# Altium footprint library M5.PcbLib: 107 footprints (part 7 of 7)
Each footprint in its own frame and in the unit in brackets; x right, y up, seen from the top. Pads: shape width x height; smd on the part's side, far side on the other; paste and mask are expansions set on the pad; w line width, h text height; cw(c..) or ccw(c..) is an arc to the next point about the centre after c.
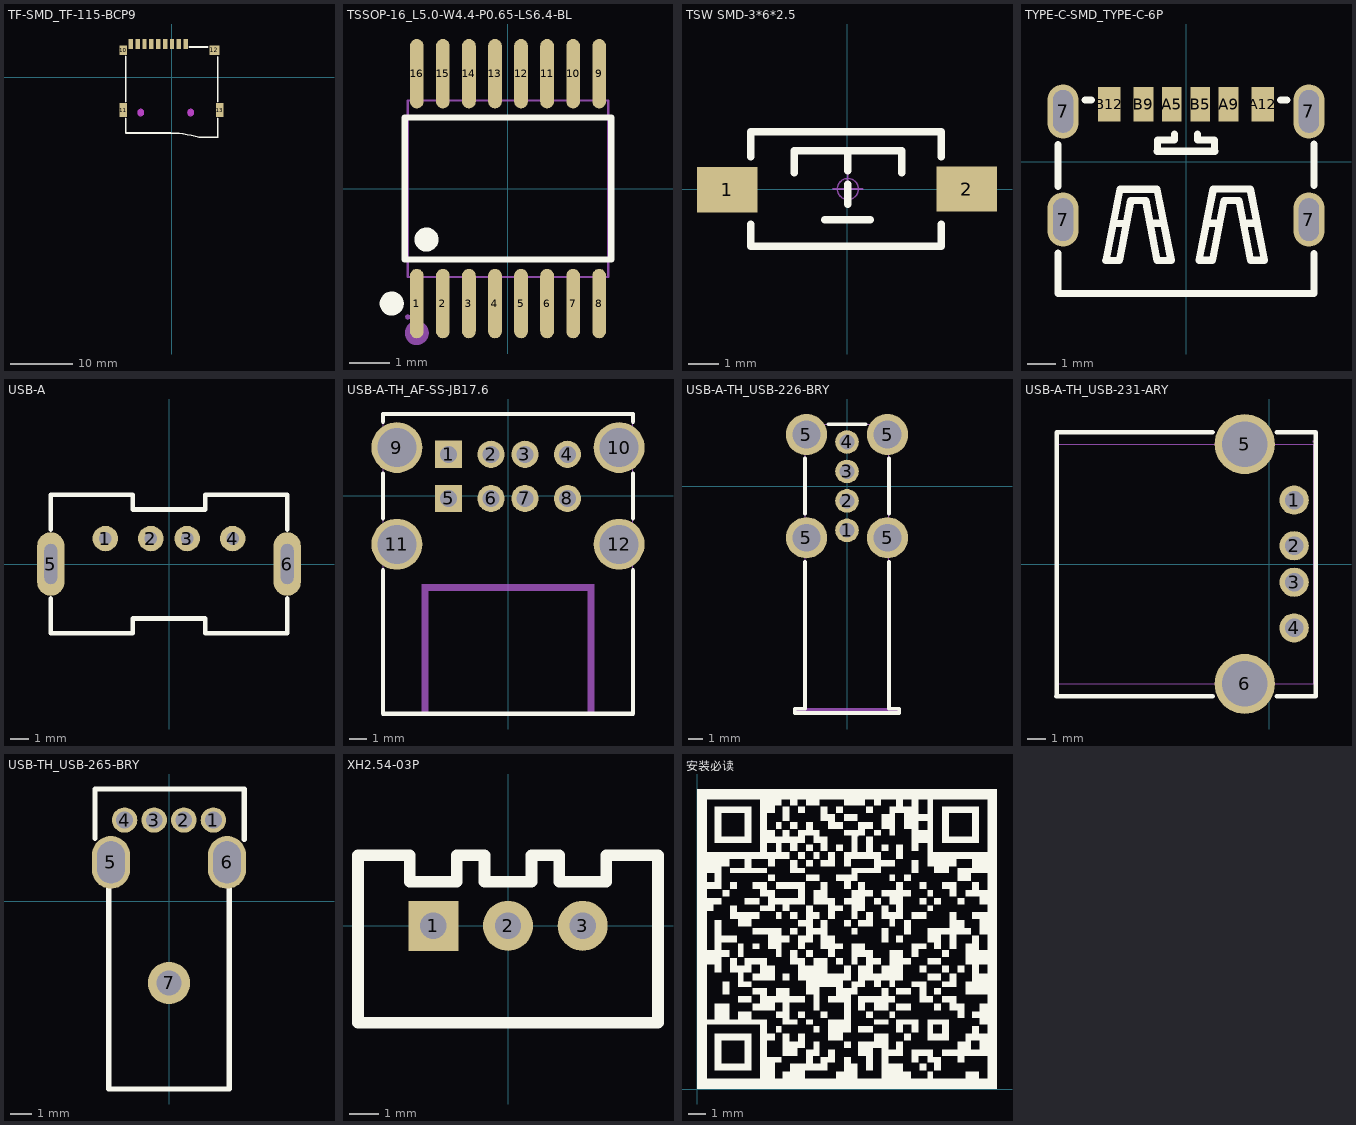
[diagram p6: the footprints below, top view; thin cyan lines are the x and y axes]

## TF-SMD_TF-115-BCP9 [mm]
pads (13):
  rect 0.7x1.6 smd: 1(2.25,5.3) 2(1.15,5.3) 3(0.05,5.3) 4(-1.05,5.3) 5(-2.15,5.3) 6(-3.25,5.3) 7(-4.35,5.3) 8(-5.45,5.3) 9(-6.55,5.3)
  rect 1.2x1.5 smd: 10(-7.75,4.3)
  rect 1.2x2.2 smd: 11(-7.75,-5.3) 13(7.75,-5.3)
  rect 1.6x1.5 smd: 12(6.85,4.3)
Top Overlay:
  lines w0.254: -7.38,-6.631 -7.38,-8.98 -2.22,-8.98 -0.14,-8.98 cw(c-0.424,-25.511) 4.41,-9.7 7.42,-9.69 ; -7.38,-3.969 -7.38,3.319 ; 2.831,4.81 5.819,4.81 ; 7.41,-9.7 7.42,-9.69 ; 7.42,-6.631 7.42,-9.69 ; 7.42,-3.969 7.42,3.28
Keep-Out Layer:
  circle w0.025: c3.05,-5.7 r0.5
  circle w0.025: c-4.95,-5.7 r0.5
  board cut-out: 3.56,-5.7 3.521,-5.895 3.411,-6.06 3.245,-6.171 3.05,-6.21 2.855,-6.171 2.69,-6.06 2.579,-5.895 2.54,-5.7 2.579,-5.505 2.69,-5.34 2.855,-5.229 3.05,-5.19 3.245,-5.229 3.411,-5.34 3.521,-5.505
  board cut-out: -4.44,-5.7 -4.479,-5.895 -4.589,-6.06 -4.755,-6.171 -4.95,-6.21 -5.145,-6.171 -5.31,-6.06 -5.421,-5.895 -5.46,-5.7 -5.421,-5.505 -5.31,-5.34 -5.145,-5.229 -4.95,-5.19 -4.755,-5.229 -4.589,-5.34 -4.479,-5.505
Keep-Out Layer:
  region: 3.56,-5.7 3.521,-5.895 3.411,-6.06 3.245,-6.171 3.05,-6.21 2.855,-6.171 2.69,-6.06 2.579,-5.895 2.54,-5.7 2.579,-5.505 2.69,-5.34 2.855,-5.229 3.05,-5.19 3.245,-5.229 3.411,-5.34 3.521,-5.505
  region: -4.44,-5.7 -4.479,-5.895 -4.589,-6.06 -4.755,-6.171 -4.95,-6.21 -5.145,-6.171 -5.31,-6.06 -5.421,-5.895 -5.46,-5.7 -5.421,-5.505 -5.31,-5.34 -5.145,-5.229 -4.95,-5.19 -4.755,-5.229 -4.589,-5.34 -4.479,-5.505
Mechanical 1:
  circle w0.025: c3.05,-5.7 r0.5
  circle w0.025: c-4.95,-5.7 r0.5
Mechanical 6:
  circle w0.4: c-4.95,-5.7 r0.2
  circle w0.4: c3.05,-5.7 r0.2
3D body: height 1.8, standoff -0.6, extent -8.025,-9.8 8.125,5.3

## TSSOP-16_L5.0-W4.4-P0.65-LS6.4-BL [mm]
pads (16):
  oval 0.343x1.731 smd: 1(-2.275,-2.866) 2(-1.625,-2.866) 3(-0.975,-2.866) 4(-0.325,-2.866) 5(0.325,-2.866) 6(0.975,-2.866) 7(1.625,-2.866) 8(2.275,-2.866) 9(2.275,2.866) 10(1.625,2.866) 11(0.975,2.866) 12(0.325,2.866) 13(-0.325,2.866) 14(-0.975,2.866) 15(-1.625,2.866) 16(-2.275,2.866)
Top Overlay:
  circle w0.3: c-2.032,-1.27 r0.15
  circle w0.3: c-2.899,-2.866 r0.15
  lines w0.152: -2.576,-1.771 -2.576,1.772 2.576,1.772 2.576,-1.771 -2.576,-1.771
Mechanical 6:
  circle w0.3: c-2.275,-3.6 r0.15
Mechanical 15:
  drawing of 37 lines, arcs and shapes, not listed

## TSW SMD-3*6*2.5 [mm]
pads (2):
  rect 2x1.5 smd: 1(-3.966,-0.01) 2(3.966,0.01)
Top Overlay:
  lines w0.254: -3.182,-1.158 -3.182,-1.89 3.118,-1.89 3.118,-1.158 ; -3.182,1.077 -3.182,1.91 3.118,1.91 3.118,1.077 ; -1.749,0.543 -1.749,1.28 1.807,1.28 1.807,0.543 ; -0.733,-1.006 0.766,-1.006 ; 0.029,-0.498 0.029,0.162 ; 0.029,0.62 0.029,1.28
Mechanical 15:
  circle w0.05: c0.029,0.01 r0.35
  lines w0.05: -0.471,0.01 0.529,0.01 ; 0.029,-0.49 0.029,0.51
3D body: height 2.59, standoff -0.03, extent -3.971,-1.867 4.029,1.633

## TYPE-C-SMD_TYPE-C-6P [mm]
pads (10):
  oval 1.1x1.9 hole 0.7 slot 1.5 at 90 deg: 7(-4.32,-2.025) 7(-4.32,1.775) 7(4.32,-2.025) 7(4.32,1.775)
  rect 0.7x1.2 smd paste-100 mask+0.051: A5(-0.5,2.025) A9(1.5,2.025) B5(0.5,2.025) B9(-1.5,2.025)
  rect 0.8x1.2 smd paste-100 mask+0.051: A12(2.7,2.025) B12(-2.7,2.025)
Top Overlay:
  lines w0.25: -4.501,-3.226 -4.501,-3.203 -4.501,-4.626 4.501,-4.626 4.501,-3.226 ; -4.5,-0.867 -4.5,0.575 -4.5,0.617 ; -3.541,2.175 -3.329,2.175 ; -1.01,0.375 1.01,0.375 ; -1,0.375 -1,0.775 -0.4,0.775 -0.4,0.975 ; 0.4,0.975 0.4,0.775 1,0.775 1,0.375 ; 3.329,2.175 3.541,2.175 ; 4.5,-0.825 4.5,0.625
  lines w0.254: -2.518,-2.158 -2.119,-2.158 ; -1.219,-2.157 -0.819,-2.157 ; 0.759,-2.153 1.158,-2.153 ; 2.058,-2.152 2.458,-2.152 ; -2.818,-3.458 -2.32,-0.956 -1.019,-0.956 -0.519,-3.458 -1.014,-3.458 -1.413,-1.358 -1.941,-1.358 -2.343,-3.458 -2.818,-3.458 ; 0.459,-3.453 0.957,-0.951 2.257,-0.951 2.758,-3.453 2.263,-3.453 1.864,-1.353 1.335,-1.353 0.934,-3.453 0.459,-3.453
Top Paste:
  drawing of 10 lines, arcs and shapes, not listed

## USB-A [mm]
pads (6):
  round 1.4 hole 0.7: 1(-3.5,1.4) 2(-1,1.4) 3(1,1.4) 4(3.5,1.4)
  oval 1.5x3.5 hole 0.7 slot 2.2 at 90 deg: 5(-6.5,0) 6(6.5,0)
Top Overlay:
  lines w0.254: -6.5,-1.9 -6.5,-3.8 -2,-3.8 -2,-3 2,-3 2,-3.8 6.5,-3.8 6.5,-1.9 ; -6.5,1.9 -6.5,3.8 -2,3.8 -2,3 2,3 2,3.8 6.5,3.8 6.5,1.9

## USB-A-TH_AF-SS-JB17.6 [mm]
pads (12):
  rect 1.6x1.6 hole 1 paste+0 mask+0.05: 1(-3.5,2.45) 5(-3.5,-0.15)
  round 1.6 hole 1 paste+0 mask+0.05: 2(-1,2.45) 3(1,2.45) 4(3.5,2.45) 6(-1,-0.15) 7(1,-0.15) 8(3.5,-0.15)
  round 3 hole 2.3 paste+0 mask+0.05: 9(-6.55,2.85) 10(6.55,2.85) 11(-6.55,-2.85) 12(6.55,-2.85)
Top Overlay:
  lines w0.254: -7.366,-4.376 -7.366,-12.827 7.366,-12.827 7.366,-4.376 ; -7.366,-1.324 -7.366,1.324 ; -7.366,4.376 -7.366,4.826 7.366,4.826 7.366,4.376 ; 7.366,-1.324 7.366,1.324
Mechanical 6:
  region: -5.08,-12.827 -5.08,-5.207 5.08,-5.207 5.08,-12.827 4.699,-12.827 4.699,-5.588 -4.699,-5.588 -4.699,-12.827
Mechanical 15:
  region: -7.285,4.75 -7.304,4.704 -7.35,4.685 -7.396,4.704 -7.415,4.75 -7.396,4.796 -7.35,4.815 -7.304,4.796
  region: 3.2,0 3.8,0 3.8,-0.3 3.2,-0.3
  region: 0.7,0 1.3,0 1.3,-0.3 0.7,-0.3
  region: -1.3,0 -0.7,0 -0.7,-0.3 -1.3,-0.3
  region: -3.8,0 -3.2,0 -3.2,-0.3 -3.8,-0.3
  region: 3.2,2.6 3.8,2.6 3.8,2.3 3.2,2.3
  region: 0.7,2.6 1.3,2.6 1.3,2.3 0.7,2.3
  region: -1.3,2.6 -0.7,2.6 -0.7,2.3 -1.3,2.3
  region: -3.8,2.6 -3.2,2.6 -3.2,2.3 -3.8,2.3
  region: -6.7,-1.85 -6.4,-1.85 -6.4,-3.85 -6.7,-3.85
  region: -6.7,3.85 -6.4,3.85 -6.4,1.85 -6.7,1.85
  region: 6.4,-1.85 6.7,-1.85 6.7,-3.85 6.4,-3.85
  region: 6.4,3.85 6.7,3.85 6.7,1.85 6.4,1.85
  lines w0.051: -7.35,-12.85 7.35,-12.85 7.35,4.75 -7.35,4.75 -7.35,-12.85

## USB-A-TH_USB-226-BRY [mm]
pads (8):
  round 1.6 hole 1: 1(0,-3) 2(0,-1) 3(0,1) 4(0,3)
  round 2.8 hole 1.9: 5(-2.75,-3.5) 5(-2.75,3.5) 5(2.75,-3.5) 5(2.75,3.5)
Top Overlay:
  lines w0.254: -2.85,-5.128 -2.85,-15.1 -3.55,-15.1 -3.55,-15.4 3.55,-15.4 3.55,-15.1 2.85,-15.1 2.85,-5.128 ; -2.85,-1.872 -2.85,1.872 ; -1.277,4.2 1.277,4.2 ; 2.85,-1.872 2.85,1.872
Mechanical 6:
  region: -3.55,-15.09 -3.55,-15.39 3.55,-15.39 3.55,-15.09
  region: 2.73,-5.13 2.97,-5.13 2.97,-15.08 2.73,-15.08
  region: -2.97,-5.13 -2.73,-5.13 -2.73,-15.08 -2.97,-15.08
Mechanical 15:
  region: 3.615,-15.4 3.596,-15.446 3.55,-15.465 3.504,-15.446 3.485,-15.4 3.504,-15.354 3.55,-15.335 3.596,-15.354
  region: 2.6,3 2.6,4.2 2.9,4.2 2.9,3
  region: 2.6,-4.1 2.6,-2.9 2.9,-2.9 2.9,-4.1
  region: -2.9,-4.1 -2.9,-2.9 -2.6,-2.9 -2.6,-4.1
  region: -2.9,3 -2.9,4.2 -2.6,4.2 -2.6,3
  region: 2.6,4.2 2.6,3 3.55,3 3.55,4.201
  region: -2.6,3 -2.6,4.2 -3.55,4.2 -3.55,2.999
  region: -2.6,-4.099 -2.6,-2.899 -3.55,-2.899 -3.55,-4.1
  region: 2.6,-2.901 2.6,-4.101 3.55,-4.101 3.55,-2.9
  region: -0.125,3.2 0.125,3.2 0.125,2.8 -0.125,2.8
  region: -0.125,1.2 0.125,1.2 0.125,0.8 -0.125,0.8
  region: -0.125,-0.8 0.125,-0.8 0.125,-1.2 -0.125,-1.2
  region: -0.125,-2.8 0.125,-2.8 0.125,-3.2 -0.125,-3.2
  lines w0.051: -3.55,-15.4 3.55,-15.4 3.55,-15.1 2.85,-15.1 2.85,4.2 -2.85,4.2 -2.85,-15.1 -3.55,-15.1 -3.55,-15.4
3D body: height 13.45, standoff -4.1, extent -3.574,-15.447 3.526,4.053

## USB-A-TH_USB-231-ARY [mm]
pads (6):
  round 1.6 hole 1: 1(1.355,3.5) 2(1.355,1) 3(1.355,-1) 4(1.355,-3.5)
  round 3.3 hole 2.5: 5(-1.355,6.57) 6(-1.355,-6.57)
Top Overlay:
  lines w0.254: -11.684,-7.239 -3.113,-7.239 ; -11.655,-7.225 -11.655,7.225 -3.118,7.225 ; 0.403,-7.239 2.54,-7.239 2.54,7.225 0.408,7.225
Mechanical 6:
  circle w0.4: c1.52,3.53 r0.2
Mechanical 15:
  region: -2.355,6.72 -0.355,6.72 -0.355,6.42 -2.355,6.42
  region: -2.355,-6.42 -0.355,-6.42 -0.355,-6.72 -2.355,-6.72
  region: 1.48,3.85 1.48,3.15 1.23,3.15 1.23,3.85
  region: 1.48,1.35 1.48,0.65 1.23,0.65 1.23,1.35
  region: 1.48,-0.65 1.48,-1.35 1.23,-1.35 1.23,-0.65
  region: 1.48,-3.15 1.48,-3.85 1.23,-3.85 1.23,-3.15
  region: 2.43,6.655 2.384,6.674 2.365,6.72 2.384,6.766 2.43,6.785 2.476,6.766 2.495,6.72 2.476,6.674
  lines w0.051: -11.57,-6.55 -3.66,-6.55 2.43,-6.55 2.43,6.55 -11.57,6.55 -11.57,-6.55
3D body: height 7.54, standoff -4, extent -11.587,-7.725 2.413,7.725

## USB-TH_USB-265-BRY [mm]
pads (7):
  round 1.2 hole 0.8: 1(2.1,3.855) 2(0.7,3.855) 3(-0.7,3.855) 4(-2.1,3.855)
  oval 1.8x2.5 hole 1.3 slot 2 at 90 deg: 5(-2.75,1.855) 6(2.75,1.855)
  round 2 hole 1.2: 7(0,-3.855)
Top Overlay:
  lines w0.254: -3.5,2.991 -3.5,5.325 3.5,5.325 ; -2.86,0.599 -2.86,-8.875 2.86,-8.875 2.86,0.652 ; 3.556,2.938 3.556,5.325
3D body: height 14.21, standoff -2.31, extent -3.822,-8.866 3.823,5.334

## XH2.54-03P [mm] "接?"
height 7
pads (3):
  rect 1.7x1.7 hole 0.9: 1(-2.54,0)
  round 1.7 hole 0.9: 2(0,0) 3(2.54,0)
Top Overlay:
  lines w0.4: -5.1,-3.3 -5.1,2.4 -3.34,2.4 -3.34,1.5 -1.74,1.5 -1.74,2.4 -0.8,2.4 -0.8,1.5 0.8,1.5 0.8,2.4 1.74,2.4 1.74,1.5 3.34,1.5 3.34,2.4 5.1,2.4 5.1,-3.3 -5.1,-3.3
3D body: height 7.03, standoff -2.47, extent -5.04,-3.3 5.04,2.4

## 安装必读 [mm]
Top Overlay:
  drawing of 1959 lines, arcs and shapes, not listed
